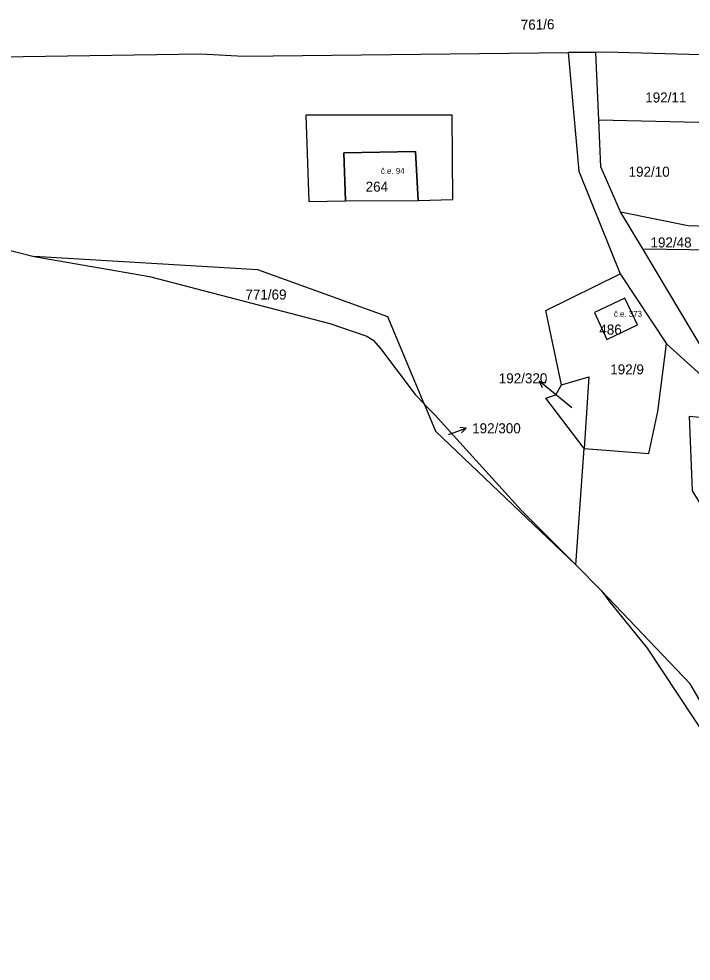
# Model space of a CAD drawing. Extents: x -887272 to -880188, y -1026687 to -1021896.
# Drawn here: x -882638.7 to -882525, y -1024208.8 to -1024049.5 of the extents above; entities that cross this region are included whole.
import ezdxf

# ---------------------------------------------------------------- set-up
doc = ezdxf.new("R2010")
doc.units = 0
for name, color, linetype in [('Definiční body', 7, 'Continuous'), ('Hranice parcel', 7, 'Continuous'), ('Parcelní čísla', 7, 'Continuous'), ('Polygon budovy', 7, 'Continuous'), ('Pop  PČ popisy', 7, 'Continuous'), ('Vnitřní kresba', 7, 'Continuous')]:
    doc.layers.add(name, color=color, linetype=linetype)

msp = doc.modelspace()

# ---------------------------------------------------------------- linework, layer by layer
at = {"layer": 'Hranice parcel'}
for p, q in [((-882541.07, -1024055.16), (-882545.75, -1024055.18)), ((-882545.75, -1024055.18), (-882543.98, -1024075.25)), ((-882539.38, -1024055.15), (-882541.07, -1024055.16)), ((-882540.58, -1024066.64), (-882541.07, -1024055.16)), ((-882516.06, -1024055.78), (-882539.38, -1024055.15)), ((-882516.01, -1024067.18), (-882540.58, -1024066.64)), ((-882543.98, -1024075.25), (-882536.95, -1024092.63)), ((-882533.15, -1024088.37), (-882536.9, -1024082.1)), ((-882663.14, -1024082.74), (-882636.1, -1024089.7)), ((-882533.15, -1024088.37), (-882520.72, -1024088.57)), ((-882636.1, -1024089.7), (-882616.57, -1024093.08)), ((-882536.95, -1024092.63), (-882529.15, -1024104.45)), ((-882543.07, -1024122.14), (-882549.54, -1024113.64)), ((-882544.44, -1024141.78), (-882543.07, -1024122.14)), ((-882544.44, -1024141.78), (-882553.65, -1024132.6)), ((-882544.44, -1024141.78), (-882540.14, -1024146.21))]:
    msp.add_line(p, q, dxfattribs=at)
for points in [[(-882731.42, -1024055.06), (-882680.72, -1024056.68), (-882649.26, -1024056.02), (-882607.88, -1024055.44), (-882600.66, -1024055.78), (-882545.75, -1024055.18)], [(-882565.28, -1024080.06), (-882565.38, -1024065.76), (-882590.14, -1024065.76), (-882589.64, -1024080.36), (-882583.42, -1024080.26), (-882571.12, -1024080.2), (-882565.28, -1024080.06)], [(-882536.9, -1024082.1), (-882540.24, -1024074.53), (-882540.58, -1024066.64)], [(-882536.9, -1024082.1), (-882525.45, -1024084.46), (-882520.44, -1024084.62)], [(-882506.08, -1024111.82), (-882518.58, -1024109.48), (-882522.71, -1024105.86), (-882533.15, -1024088.37)], [(-882570.12, -1024114.61), (-882576.24, -1024099.88), (-882598.26, -1024091.94), (-882636.1, -1024089.7)], [(-882616.57, -1024093.08), (-882586.06, -1024100.99), (-882579.82, -1024103.15), (-882578.76, -1024103.81), (-882577.49, -1024105.21), (-882571.64, -1024113.03), (-882570.12, -1024114.61)], [(-882546.91, -1024111.39), (-882549.52, -1024098.83), (-882536.95, -1024092.63)], [(-882534.06, -1024101.25), (-882536.19, -1024096.74), (-882541.31, -1024099.15), (-882539.22, -1024103.69), (-882534.06, -1024101.25)], [(-882543.07, -1024122.14), (-882532.14, -1024123), (-882530.59, -1024115.87), (-882529.15, -1024104.45)], [(-882529.15, -1024104.45), (-882519.64, -1024113.02), (-882509.9, -1024118.11)], [(-882546.91, -1024111.39), (-882542.24, -1024110.04), (-882543.07, -1024122.14)], [(-882549.54, -1024113.64), (-882547.84, -1024113.05), (-882546.91, -1024111.39)], [(-882553.65, -1024132.6), (-882563.04, -1024122.28), (-882568.27, -1024116.52), (-882569.89, -1024114.84), (-882570.12, -1024114.61)], [(-882570.12, -1024114.61), (-882568.22, -1024119.18), (-882544.44, -1024141.78)], [(-882516.17, -1024143.02), (-882524.72, -1024129.29), (-882525.26, -1024116.69), (-882509.9, -1024118.11)], [(-882501.82, -1024208.81), (-882505.78, -1024194.82), (-882525.14, -1024161.92), (-882540.14, -1024146.21)], [(-882540.14, -1024146.21), (-882538.86, -1024147.89), (-882532.4, -1024155.87), (-882516.84, -1024179.4), (-882505.08, -1024201.85), (-882501.82, -1024208.81)]]:
    msp.add_lwpolyline(points, dxfattribs=at)
at = {"layer": 'Polygon budovy'}
for points in [[(-882571.12, -1024080.2), (-882571.56, -1024071.92), (-882583.7, -1024072.14), (-882583.42, -1024080.26)], [(-882536.19, -1024096.74), (-882541.31, -1024099.15), (-882539.22, -1024103.69), (-882534.06, -1024101.25)]]:
    msp.add_lwpolyline(points, close=True, dxfattribs=at)
at = {"layer": 'Pop  PČ popisy'}
for p, q in [((-882548.31, -1024112.67), (-882550.64, -1024110.78)), ((-882550.64, -1024110.78), (-882549.55, -1024111.02)), ((-882550.64, -1024110.78), (-882550.18, -1024111.8)), ((-882545.12, -1024115.28), (-882548.31, -1024112.67)), ((-882565.84, -1024119.69), (-882563, -1024118.71)), ((-882563, -1024118.71), (-882564.11, -1024118.57)), ((-882563, -1024118.71), (-882563.79, -1024119.51)), ((-882565.99, -1024119.74), (-882565.84, -1024119.69))]:
    msp.add_line(p, q, dxfattribs=at)
at = {"layer": 'Vnitřní kresba'}
for p, q in [((-882583.7, -1024072.14), (-882571.56, -1024071.92)), ((-882583.42, -1024080.26), (-882583.7, -1024072.14)), ((-882571.56, -1024071.92), (-882571.12, -1024080.2))]:
    msp.add_line(p, q, dxfattribs=at)

# ---------------------------------------------------------------- texts
at = {"layer": 'Definiční body'}
for s, p in [('č.e. 94', (-882577.44, -1024075.7)), ('č.e. 373', (-882538.03, -1024099.87))]:
    msp.add_text(s, height=1, dxfattribs=at).set_placement(p)
at = {"layer": 'Parcelní čísla'}
msp.add_text('761/6', height=1.7, rotation=1, dxfattribs=at).set_placement((-882553.76, -1024051.36))
for s, p in [('192/11', (-882532.72, -1024063.64)), ('192/10', (-882535.54, -1024076.19)), ('264', (-882580.02, -1024078.72)), ('192/48', (-882531.83, -1024088.15)), ('771/69', (-882600.36, -1024096.96)), ('486', (-882540.49, -1024102.88)), ('192/9', (-882538.64, -1024109.61)), ('192/320', (-882557.5, -1024111.12)), ('192/300', (-882562, -1024119.57))]:
    msp.add_text(s, height=1.7, dxfattribs=at).set_placement(p)

doc.saveas('drawing.dxf')
